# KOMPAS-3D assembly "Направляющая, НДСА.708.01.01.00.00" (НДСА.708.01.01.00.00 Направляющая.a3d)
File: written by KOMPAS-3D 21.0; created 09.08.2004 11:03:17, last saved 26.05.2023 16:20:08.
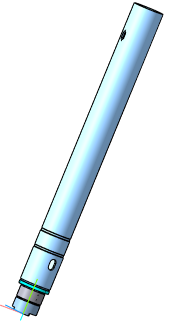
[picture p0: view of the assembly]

Document properties: Полное имя файла: C:\Users\s.pischagina\Desktop\PLM\НДСА.708.01.01.00.00 Направляющая.a3d; Автор: Устинов А.В.; Организация: Эсто-вакуум

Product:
- Part/product: Направляющая  | designation НДСА.708.01.01.00.00
    Масса: 36.462462
    Форматы листов документа: A0
    additional columns: <item xmlns="http://appius.ru/pdm" xmlns:xs="http://www.w3.org/2001/XMLSchema" x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; <item xmlns="http://appius.ru/pdm" xmlns:xs="http://www.w3.org/2001/XMLSchema" x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; <item xmlns="http://appius.ru/pdm" xmlns:xs="http://www.w3.org/2001/XMLSchema" x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; <item xmlns="http://appius.ru/pdm" xmlns:xs="http://www.w3.org/2001/XMLSchema" x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; <item xmlns="http://appius.ru/pdm" xmlns:xs="http://www.w3.org/2001/XMLSchema" x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; <item xmlns="http://appius.ru/pdm" xmlns:xs="http://www.w3.org/2001/XMLSchema" x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
  - Component [detail]: Труба  | designation НДСА.014.01.08.04.04  | pos. 4  | Материал: Труба$d140х10 ГОСТ 8732-78;20 ГОСТ 8731-74$ (density 7859 kg/m3); Масса: 32.921192; Форматы листов документа: A4; additional columns: <item xmlns="http://appius.ru/pdm" xmlns:xs="http://www.w3.org/2001/XMLSchema" x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; <item xmlns="http://appius.ru/pdm" xmlns:xs="http://www.w3.org/2001/XMLSchema" x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; <item xmlns="http://appius.ru/pdm" xmlns:xs="http://www.w3.org/2001/XMLSchema" x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; <item xmlns="http://appius.ru/pdm" xmlns:xs="http://www.w3.org/2001/XMLSchema" x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; <item xmlns="http://appius.ru/pdm" xmlns:xs="http://www.w3.org/2001/XMLSchema" x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; <item xmlns="http://appius.ru/pdm" xmlns:xs="http://www.w3.org/2001/XMLSchema" x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; source file: НДСА.014.01.08.04.04 Труба.CDW, НДСА.014.01.08.04.04 Труба.m3d
  - Component [detail]: Труба  | designation НДСА.014.01.08.04.02  | pos. 3  | Материал: Труба$d114х8 ГОСТ 8732-78;20 ГОСТ 8731-74$ (density 7859 kg/m3); Масса: 1.170395; Форматы листов документа: A4; additional columns: <item xmlns="http://appius.ru/pdm" xmlns:xs="http://www.w3.org/2001/XMLSchema" x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; <item xmlns="http://appius.ru/pdm" xmlns:xs="http://www.w3.org/2001/XMLSchema" x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; <item xmlns="http://appius.ru/pdm" xmlns:xs="http://www.w3.org/2001/XMLSchema" x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; <item xmlns="http://appius.ru/pdm" xmlns:xs="http://www.w3.org/2001/XMLSchema" x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; <item xmlns="http://appius.ru/pdm" xmlns:xs="http://www.w3.org/2001/XMLSchema" x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; <item xmlns="http://appius.ru/pdm" xmlns:xs="http://www.w3.org/2001/XMLSchema" x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; source file: НДСА.014.01.08.04.02 Труба.CDW, НДСА.014.01.08.04.02 Труба.m3d
  - Component [detail]: Втулка  | designation НДСА.014.01.08.04.01  | pos. 2  | Материал: Сталь 20 ГОСТ 1050-88 (density 7859 kg/m3); Масса: 1.411167; Форматы листов документа: A4; additional columns: <item xmlns="http://appius.ru/pdm" xmlns:xs="http://www.w3.org/2001/XMLSchema" x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; <item xmlns="http://appius.ru/pdm" xmlns:xs="http://www.w3.org/2001/XMLSchema" x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; <item xmlns="http://appius.ru/pdm" xmlns:xs="http://www.w3.org/2001/XMLSchema" x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; <item xmlns="http://appius.ru/pdm" xmlns:xs="http://www.w3.org/2001/XMLSchema" x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; <item xmlns="http://appius.ru/pdm" xmlns:xs="http://www.w3.org/2001/XMLSchema" x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; <item xmlns="http://appius.ru/pdm" xmlns:xs="http://www.w3.org/2001/XMLSchema" x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; source file: НДСА.014.01.08.04.01 Втулка.CDW, НДСА.014.01.08.04.01 Втулка.m3d
  - Component [detail]: Втулка  | designation НДСА.014.01.08.04.03  | pos. 1  | Материал: Сталь 20 ГОСТ 1050-88 (density 7859 kg/m3); Масса: 0.959708; Форматы листов документа: A4; additional columns: <item xmlns="http://appius.ru/pdm" xmlns:xs="http://www.w3.org/2001/XMLSchema" x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; <item xmlns="http://appius.ru/pdm" xmlns:xs="http://www.w3.org/2001/XMLSchema" x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; <item xmlns="http://appius.ru/pdm" xmlns:xs="http://www.w3.org/2001/XMLSchema" x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; <item xmlns="http://appius.ru/pdm" xmlns:xs="http://www.w3.org/2001/XMLSchema" x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; <item xmlns="http://appius.ru/pdm" xmlns:xs="http://www.w3.org/2001/XMLSchema" x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; <item xmlns="http://appius.ru/pdm" xmlns:xs="http://www.w3.org/2001/XMLSchema" x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; source file: НДСА.014.01.08.04.03 Втулка.CDW, НДСА.014.01.08.04.03 Втулка.m3d

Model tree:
1. Плоскость XY
2. Плоскость ZX
3. Плоскость ZY
4. Начало координат
5. Ось пересечения двух плоскостей:1
6. Эскиз:1  (labels: Операция выдавливания:1)
7. Элемент выдавливания:1
     Расстояние 2 = 2
8. Эскиз:2  (with: Элемент выдавливания:1)
9. Элемент выдавливания:2
     Расстояние 2 = 12
10. Эскиз:3  (with: Элемент выдавливания:1)
11. Элемент выдавливания:3
     Расстояние 2 = 25
12. Эскиз:4  (with: Элемент выдавливания:3)
13. Элемент выдавливания:4
     Расстояние 2 = 20
14. Фаска:1  (with: Элемент выдавливания:4)
     Угол = 45; Длина 1 = 2; Длина 2 = 2
15. Скругление:1  (with: Элемент выдавливания:3, Элемент выдавливания:2)
     Радиус = 4; Полуось 2 = 1; Коэффициент = 0.5; Хорда = 1
16. Эскиз:5  (with: Элемент выдавливания:4)
17. Элемент выдавливания:5
     Расстояние 2 = 20
18. Скругление:2  (with: Элемент выдавливания:5)
     Радиус = 4; Полуось 2 = 1; Коэффициент = 0.5; Хорда = 1
19. Эскиз:6
20. Элемент выдавливания:6
     Расстояние 1 = 70
21. Условное изображение резьбы:1  (with: Элемент выдавливания:6)  (labels: M3; cil0_24705-2004 coarse)
     Длина резьбы = 8.02296; Шаг резьбы = 0.5; Номинальный диаметр резьбы = 3
22. Подгонка:1  (with: Элемент выдавливания:6)
23. Условное изображение резьбы:2  (with: Элемент выдавливания:6)  (labels: M3; cil0_24705-2004 coarse)
     Длина резьбы = 8.02296; Шаг резьбы = 0.5; Номинальный диаметр резьбы = 3
24. Подгонка:2  (with: Элемент выдавливания:6)
25. Эскиз:7  (labels: Операция выдавливания:1)
26. Элемент выдавливания:7
     Расстояние 2 = 1074
27. Эскиз:8  (with: Элемент выдавливания:7)
28. Элемент выдавливания:8
     Расстояние 1 = 10
29. Фаска:2  (with: Элемент выдавливания:8)
     Угол = 45; Длина 1 = 1; Длина 2 = 1
30. Скругление:3  (with: Элемент выдавливания:8)
     Радиус = 1; Полуось 2 = 1; Коэффициент = 0.5; Хорда = 1
31. Эскиз:9  (with: Элемент выдавливания:7)
32. Элемент выдавливания:9
     Расстояние 2 = 77
33. Фаска:3  (with: Элемент выдавливания:9)
     Угол = 45; Длина 1 = 1; Длина 2 = 1
34. Эскиз:10  (with: Элемент выдавливания:9)
35. Элемент выдавливания:10
     Расстояние 1 = 10
36. Фаска:4  (with: Элемент выдавливания:10)
     Угол = 45; Длина 1 = 1; Длина 2 = 1
37. Скругление:4  (with: Элемент выдавливания:10)
     Радиус = 1; Полуось 2 = 1; Коэффициент = 0.5; Хорда = 1
38. Скругление:5  (with: Элемент выдавливания:10)
     Радиус = 2; Полуось 2 = 1; Коэффициент = 0.5; Хорда = 1
39. Эскиз:11
40. Элемент выдавливания:11
     Расстояние 1 = 70; Расстояние 2 = 70
41. Эскиз:12
42. Элемент выдавливания:12
     Расстояние 2 = 70
43. Эскиз:13  (labels: Операция выдавливания:1)
44. Элемент выдавливания:13
     Расстояние 2 = 1055
45. Эскиз:14  (with: Элемент выдавливания:13)
46. Элемент выдавливания:14
     Расстояние 2 = 10
47. Условное изображение резьбы:3  (with: Элемент выдавливания:14)  (labels: M4; cil0_24705-2004 coarse)
     Длина резьбы = 6.03334; Шаг резьбы = 0.7; Номинальный диаметр резьбы = 4
48. Подгонка:3  (with: Элемент выдавливания:14)
49. Условное изображение резьбы:4  (with: Элемент выдавливания:14)  (labels: M4; cil0_24705-2004 coarse)
     Длина резьбы = 6.03334; Шаг резьбы = 0.7; Номинальный диаметр резьбы = 4
50. Подгонка:4  (with: Элемент выдавливания:14)
51. Условное изображение резьбы:5  (with: Элемент выдавливания:14)  (labels: M4; cil0_24705-2004 coarse)
     Длина резьбы = 6.03334; Шаг резьбы = 0.7; Номинальный диаметр резьбы = 4
52. Подгонка:5  (with: Элемент выдавливания:14)
53. Условное изображение резьбы:6  (with: Элемент выдавливания:14)  (labels: M4; cil0_24705-2004 coarse)
     Длина резьбы = 6.03334; Шаг резьбы = 0.7; Номинальный диаметр резьбы = 4
54. Подгонка:6  (with: Элемент выдавливания:14)
55. Условное изображение резьбы:7  (with: Элемент выдавливания:14)  (labels: M4; cil0_24705-2004 coarse)
     Длина резьбы = 6.03334; Шаг резьбы = 0.7; Номинальный диаметр резьбы = 4
56. Подгонка:7  (with: Элемент выдавливания:14)
57. Эскиз:15
58. Элемент выдавливания:15
     Расстояние 2 = 70
59. Условное изображение резьбы:8  (with: Элемент выдавливания:15)  (labels: M3; cil0_24705-2004 coarse)
     Длина резьбы = 8.01875; Шаг резьбы = 0.5; Номинальный диаметр резьбы = 3
60. Подгонка:8  (with: Элемент выдавливания:15)
61. Условное изображение резьбы:9  (with: Элемент выдавливания:15)  (labels: M3; cil0_24705-2004 coarse)
     Длина резьбы = 8.01875; Шаг резьбы = 0.5; Номинальный диаметр резьбы = 3
62. Подгонка:9  (with: Элемент выдавливания:15)
63. Сечение поверхностью:1  (labels: Операция вращения:1; Операция вращения:1; Операция вращения:1; Операция вращения:1)
     Расстояние = -1324

Referenced files in C:\Users\s.pischagina\Desktop\PLM\: НДСА.014.01.08.04.03 Втулка.m3d, НДСА.014.01.08.04.03 Втулка.CDW, НДСА.014.01.08.04.01 Втулка.m3d, НДСА.014.01.08.04.01 Втулка.CDW, НДСА.014.01.08.04.02 Труба.m3d, НДСА.014.01.08.04.02 Труба.CDW, НДСА.014.01.08.04.04 Труба.m3d, НДСА.014.01.08.04.04 Труба.CDW
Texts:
  НДСА.014.01.08.04.03
  НДСА.014.01.08.04.01
  НДСА.014.01.08.04.02
  НДСА.014.01.08.04.04
  НДСА.708.01.01.00.00
  НДСА.014.01.08.04.03 Втулка
  НДСА.014.01.08.04.01 Втулка
  НДСА.014.01.08.04.02 Труба
  НДСА.014.01.08.04.04 Труба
